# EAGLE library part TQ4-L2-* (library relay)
LOW PROFILE 2 FORM C RELAY NAiS 2 coil latching Source: http://www.mew-europe.com/.. en_ds_61020_0001.pdf
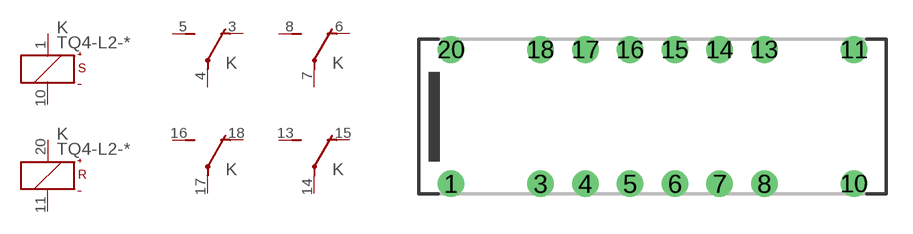
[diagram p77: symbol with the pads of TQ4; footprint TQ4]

Designator prefix K; gates S=K+-S R=K+-R 1=U 2=U 3=U 4=U

## TQ4-L2-3V (OC_FARNELL: unknown; OC_NEWARK: unknown), TQ4-L2-4.5V (OC_FARNELL: unknown; OC_NEWARK: unknown), TQ4-L2-5V (MF: AROMAT/ MATSUSHITA; MPN: TQ4-L2-5V; OC_FARNELL: unknown; OC_NEWARK: 64K3208), TQ4-L2-6V (OC_FARNELL: unknown; OC_NEWARK: unknown), TQ4-L2-9V (OC_FARNELL: unknown; OC_NEWARK: unknown), TQ4-L2-12V (MF: AROMAT/ MATSUSHITA; MPN: TQ4-L2-12V; OC_FARNELL: unknown; OC_NEWARK: 90F5822), TQ4-L2-24V (MPN: TQ4-L2-24V; OC_FARNELL: unknown; OC_NEWARK: 15P9807)  [TQ4]
1  S:+  pas
3  1:O  pas
4  1:P  pas
5  1:S  pas
6  2:O  pas
7  2:P  pas
8  2:S  pas
10  S:-  pas
11  R:-  pas
13  4:S  pas
14  4:P  pas
15  4:O  pas
16  3:S  pas
17  3:P  pas
18  3:O  pas
20  R:+  pas

## Footprint TQ4 (pad centres in mm)
LOW PROFILE 2 FORM C RELAY NAiS Source: http://www.mew-europe.com/.. en_ds_61020_0001.pdf
drill 1 round: 1 -11.43,-3.81; 3 -6.35,-3.81; 4 -3.81,-3.81; 5 -1.27,-3.81; 6 1.27,-3.81; 7 3.81,-3.81; 8 6.35,-3.81; 10 11.43,-3.81; 11 11.43,3.81; 13 6.35,3.81; 14 3.81,3.81; 15 1.27,3.81; 16 -1.27,3.81; 17 -3.81,3.81; 18 -6.35,3.81; 20 -11.43,3.81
